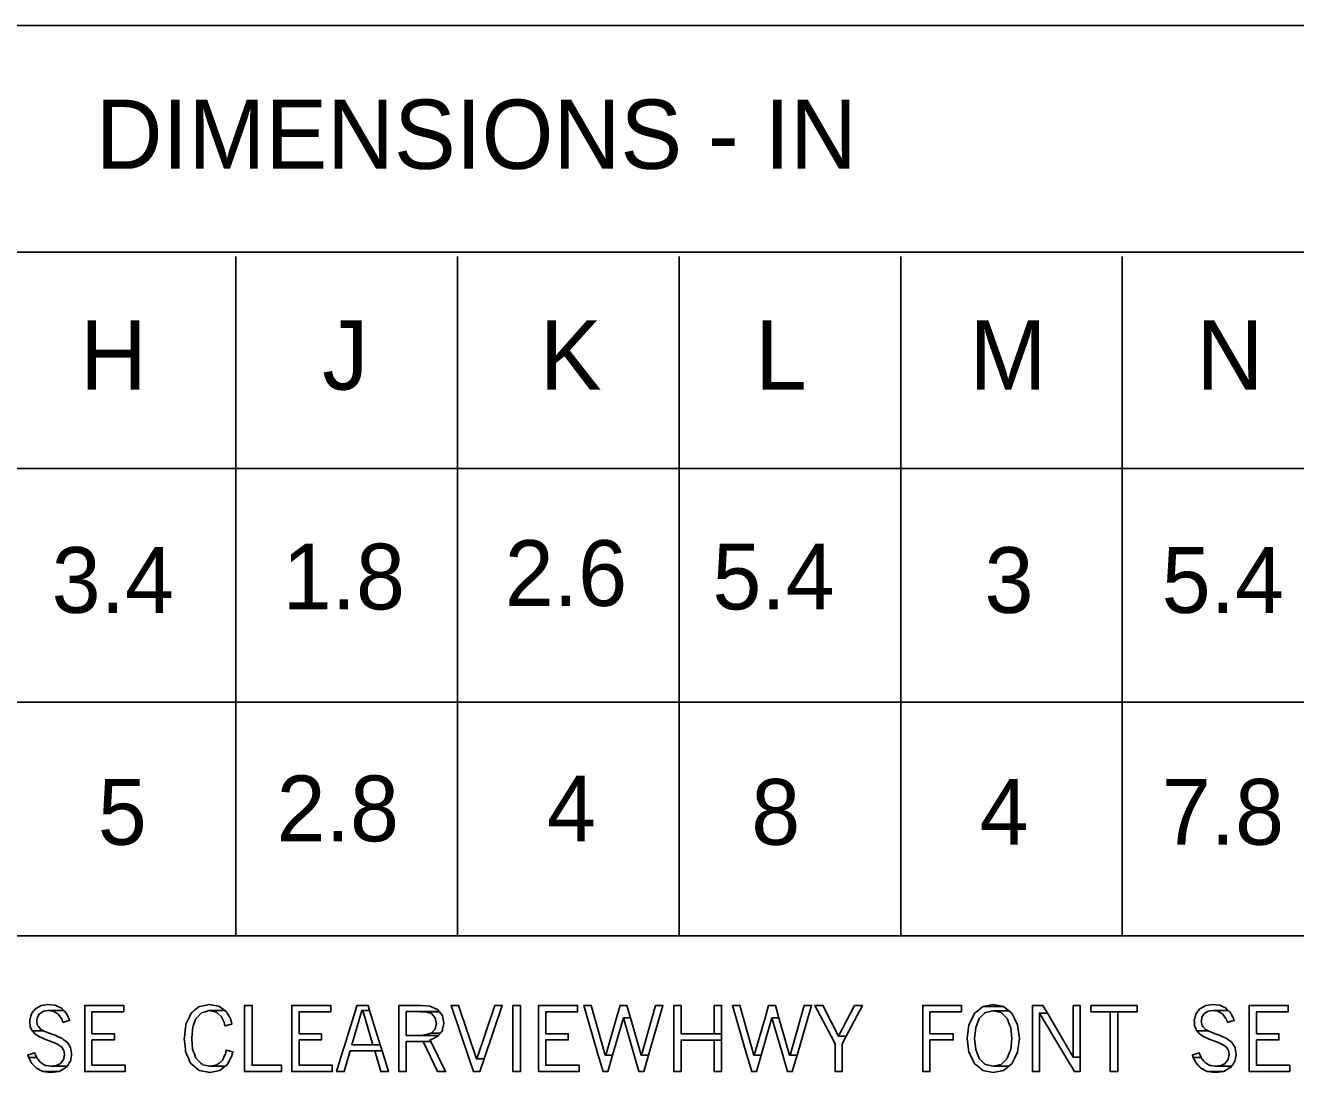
# Model space of a CAD drawing. Extents: x 0.013 to 0.187, y -0.092 to 0.261.
# Drawn here: x 0.09331 to 0.13917, y 0.0569 to 0.09473 of the extents above; entities that cross this region are included whole.
import ezdxf

# ---------------------------------------------------------------- set-up
doc = ezdxf.new("R2010")
doc.units = 0
doc.layers.add('3', color=7, linetype='Continuous')

msp = doc.modelspace()

# ---------------------------------------------------------------- linework, layer by layer
at = {"layer": '3'}
for p, q in [((0.032451, 0.094728), (0.186512, 0.094728)), ((0.186512, 0.086538), (0.032451, 0.086538)), ((0.100908, 0.086386), (0.100908, 0.061842)), ((0.108908, 0.086386), (0.108908, 0.061842)), ((0.116908, 0.086386), (0.116908, 0.061842)), ((0.124908, 0.086386), (0.124908, 0.061842)), ((0.132908, 0.086386), (0.132908, 0.061842)), ((0.032384, 0.078726), (0.186512, 0.078726)), ((0.032451, 0.070284), (0.186512, 0.070284)), ((0.032519, 0.061842), (0.186512, 0.061842))]:
    msp.add_line(p, q, dxfattribs=at)
for points in [[(0.093526, 0.058465), (0.093549, 0.058415), (0.093964, 0.058415), (0.093867, 0.058465), (0.093778, 0.05857), (0.093746, 0.058609), (0.093722, 0.058715), (0.093714, 0.058756), (0.093718, 0.058784), (0.093722, 0.058806), (0.09373, 0.058856), (0.093731, 0.058862), (0.093739, 0.05891), (0.093809, 0.059016), (0.093821, 0.059034), (0.093832, 0.059041), (0.093848, 0.059051), (0.093958, 0.059118), (0.093961, 0.059119), (0.094131, 0.059146), (0.09469, 0.059146), (0.094631, 0.059208), (0.094611, 0.059229), (0.094411, 0.059325), (0.094379, 0.05934), (0.094125, 0.059367), (0.094125, 0.059367), (0.093968, 0.05934), (0.093878, 0.059325), (0.093707, 0.059229), (0.093668, 0.059208), (0.093618, 0.059146), (0.093596, 0.059119), (0.093595, 0.059118), (0.09354, 0.059051), (0.093532, 0.059041), (0.093529, 0.059034), (0.093524, 0.059016), (0.093493, 0.05891), (0.093479, 0.058862), (0.093477, 0.058856), (0.093462, 0.058806), (0.093463, 0.058784), (0.093465, 0.058756), (0.093468, 0.058715), (0.093476, 0.058609), (0.093478, 0.05857)], [(0.095448, 0.057172), (0.095448, 0.056942), (0.096911, 0.056942), (0.096911, 0.057172), (0.09571, 0.057172), (0.09571, 0.058085), (0.096522, 0.058085), (0.096522, 0.058306), (0.09571, 0.058306), (0.09571, 0.059103), (0.096856, 0.059103), (0.096856, 0.059329), (0.095448, 0.059329), (0.095448, 0.059103), (0.095448, 0.058306), (0.095448, 0.058085)], [(0.099593, 0.056975), (0.099961, 0.056904), (0.100325, 0.056975), (0.100329, 0.056978), (0.10052, 0.057131), (0.099972, 0.057131), (0.099705, 0.05719), (0.099701, 0.057191), (0.0997, 0.057192), (0.099699, 0.057192), (0.099642, 0.057249), (0.099641, 0.057249), (0.099535, 0.057355), (0.099465, 0.057423), (0.099439, 0.057494), (0.099409, 0.057576), (0.099388, 0.057633), (0.099379, 0.057658), (0.099345, 0.057751), (0.099313, 0.058135), (0.099312, 0.058158), (0.099349, 0.058539), (0.099368, 0.058592), (0.099388, 0.058651), (0.09939, 0.058656), (0.099414, 0.058722), (0.099457, 0.058841), (0.099479, 0.058864), (0.099528, 0.058915), (0.099658, 0.059051), (0.099664, 0.059057), (0.099762, 0.059087), (0.099832, 0.059108), (0.099832, 0.059108), (0.09994, 0.059141), (0.100513, 0.059141), (0.100313, 0.059287), (0.100313, 0.059287), (0.100284, 0.059308), (0.099942, 0.059367), (0.099941, 0.059367), (0.099675, 0.059308), (0.099578, 0.059287), (0.099403, 0.059141), (0.099364, 0.059108), (0.099339, 0.059087), (0.099303, 0.059057), (0.099296, 0.059051), (0.09923, 0.058915), (0.099205, 0.058864), (0.099194, 0.058841), (0.099136, 0.058722), (0.099104, 0.058656), (0.099102, 0.058651), (0.099095, 0.058592), (0.099089, 0.058539), (0.099045, 0.058158), (0.099043, 0.058135), (0.099083, 0.057751), (0.099093, 0.057658), (0.099096, 0.057633), (0.099121, 0.057576), (0.099158, 0.057494), (0.09919, 0.057423), (0.09922, 0.057355), (0.099268, 0.057249), (0.099333, 0.057192), (0.099335, 0.057191), (0.099336, 0.05719), (0.099403, 0.057131), (0.099578, 0.056978)], [(0.101221, 0.057172), (0.101221, 0.056942), (0.102557, 0.056942), (0.102557, 0.057172), (0.10149, 0.057172), (0.10149, 0.059329), (0.101221, 0.059329)], [(0.102924, 0.057172), (0.102924, 0.056942), (0.104387, 0.056942), (0.104387, 0.057172), (0.103185, 0.057172), (0.103185, 0.058085), (0.103997, 0.058085), (0.103997, 0.058306), (0.103185, 0.058306), (0.103185, 0.059103), (0.104331, 0.059103), (0.104331, 0.059329), (0.102924, 0.059329), (0.102924, 0.059103), (0.102924, 0.058306), (0.102924, 0.058085)], [(0.104771, 0.057685), (0.104542, 0.056942), (0.10482, 0.056942), (0.105033, 0.057685), (0.106184, 0.057685), (0.106116, 0.057906), (0.105097, 0.057906), (0.105454, 0.059149), (0.105733, 0.059149), (0.105678, 0.059329), (0.105277, 0.059329), (0.105222, 0.059149), (0.104839, 0.057906)], [(0.106791, 0.058024), (0.106791, 0.056942), (0.107051, 0.056942), (0.107051, 0.058024), (0.107949, 0.058024), (0.107918, 0.058086), (0.10802, 0.058122), (0.108207, 0.058228), (0.108222, 0.058246), (0.107051, 0.058246), (0.107051, 0.058249), (0.107051, 0.058264), (0.107051, 0.058332), (0.107051, 0.058428), (0.107051, 0.058472), (0.107051, 0.058676), (0.107051, 0.058696), (0.107051, 0.058887), (0.107051, 0.058964), (0.107051, 0.059034), (0.107051, 0.059093), (0.107051, 0.059104), (0.107051, 0.059106), (0.108243, 0.059106), (0.108183, 0.059179), (0.107907, 0.059298), (0.10759, 0.059326), (0.107461, 0.059329), (0.106791, 0.059329), (0.106791, 0.059326), (0.106791, 0.059298), (0.106791, 0.059179), (0.106791, 0.059106), (0.106791, 0.059104), (0.106791, 0.059093), (0.106791, 0.059034), (0.106791, 0.058964), (0.106791, 0.058887), (0.106791, 0.058696), (0.106791, 0.058676), (0.106791, 0.058472), (0.106791, 0.058428), (0.106791, 0.058332), (0.106791, 0.058264), (0.106791, 0.058249), (0.106791, 0.058246), (0.106791, 0.058228), (0.106791, 0.058122), (0.106791, 0.058086)], [(0.109329, 0.057395), (0.109482, 0.056942), (0.109714, 0.056942), (0.109867, 0.057395), (0.109592, 0.057395), (0.108947, 0.059329), (0.108677, 0.059329)], [(0.110255, 0.059329), (0.109611, 0.057395), (0.109867, 0.057395), (0.110524, 0.059329)], [(0.11091, 0.059329), (0.11091, 0.056942), (0.111178, 0.056942), (0.111178, 0.059329)], [(0.111834, 0.057172), (0.111834, 0.056942), (0.113297, 0.056942), (0.113297, 0.057172), (0.112096, 0.057172), (0.112096, 0.058085), (0.112908, 0.058085), (0.112908, 0.058306), (0.112096, 0.058306), (0.112096, 0.059103), (0.113242, 0.059103), (0.113242, 0.059329), (0.111834, 0.059329), (0.111834, 0.059103), (0.111834, 0.058306), (0.111834, 0.058085)], [(0.113992, 0.057538), (0.114165, 0.056942), (0.114336, 0.056942), (0.114508, 0.057538), (0.114243, 0.057538), (0.113735, 0.059329), (0.11347, 0.059329)], [(0.114647, 0.058879), (0.11426, 0.057538), (0.114508, 0.057538), (0.114898, 0.058879), (0.115149, 0.058879), (0.115019, 0.059329), (0.114777, 0.059329)], [(0.116061, 0.059329), (0.115553, 0.057538), (0.115804, 0.057538), (0.116326, 0.059329)], [(0.116721, 0.058076), (0.116721, 0.056942), (0.116981, 0.056942), (0.116981, 0.058076), (0.118439, 0.058076), (0.118439, 0.058308), (0.116981, 0.058308), (0.116981, 0.059329), (0.116721, 0.059329), (0.116721, 0.058308)], [(0.11818, 0.059329), (0.11818, 0.058308), (0.118439, 0.058308), (0.118439, 0.059329)], [(0.119356, 0.057538), (0.119529, 0.056942), (0.1197, 0.056942), (0.119872, 0.057538), (0.119607, 0.057538), (0.119099, 0.059329), (0.118834, 0.059329)], [(0.120011, 0.058879), (0.119624, 0.057538), (0.119872, 0.057538), (0.120262, 0.058879), (0.120513, 0.058879), (0.120383, 0.059329), (0.120141, 0.059329)], [(0.121425, 0.059329), (0.120917, 0.057538), (0.121168, 0.057538), (0.12169, 0.059329)], [(0.122539, 0.057948), (0.122539, 0.056942), (0.1228, 0.056942), (0.1228, 0.057948), (0.122945, 0.058225), (0.122669, 0.058225), (0.1221, 0.059329), (0.121812, 0.059329), (0.122393, 0.058225)], [(0.123238, 0.059329), (0.122669, 0.058225), (0.122945, 0.058225), (0.123526, 0.059329)], [(0.125704, 0.058083), (0.125704, 0.056942), (0.125966, 0.056942), (0.125966, 0.058083), (0.126808, 0.058083), (0.126808, 0.058308), (0.125966, 0.058308), (0.125966, 0.059103), (0.127102, 0.059103), (0.127102, 0.059329), (0.125704, 0.059329), (0.125704, 0.059103), (0.125704, 0.058308)], [(0.12788, 0.05698), (0.128251, 0.056903), (0.128622, 0.05698), (0.128811, 0.057133), (0.12825, 0.057133), (0.127968, 0.057197), (0.127939, 0.057225), (0.127747, 0.057409), (0.127657, 0.057637), (0.127617, 0.057738), (0.127575, 0.058135), (0.127617, 0.058532), (0.127657, 0.058633), (0.127747, 0.058861), (0.127939, 0.059045), (0.127968, 0.059073), (0.12825, 0.059138), (0.128811, 0.059138), (0.128622, 0.05929), (0.127879, 0.05929), (0.127691, 0.059138), (0.127611, 0.059073), (0.127577, 0.059045), (0.127485, 0.058861), (0.127373, 0.058633), (0.127359, 0.058532), (0.127308, 0.058135), (0.127359, 0.057738), (0.127373, 0.057637), (0.127485, 0.057409), (0.127577, 0.057225), (0.127611, 0.057197), (0.127691, 0.057133)], [(0.128251, 0.059367), (0.12788, 0.05929), (0.128622, 0.05929)], [(0.129667, 0.057465), (0.129667, 0.056942), (0.129915, 0.056942), (0.129915, 0.057465), (0.129915, 0.059054), (0.130203, 0.059054), (0.130041, 0.059329), (0.129667, 0.059329), (0.129667, 0.059054)], [(0.131137, 0.059329), (0.131137, 0.057465), (0.131385, 0.057465), (0.131385, 0.059329)], [(0.131779, 0.059329), (0.131779, 0.059099), (0.133442, 0.059099), (0.133442, 0.059329)], [(0.135571, 0.058465), (0.135594, 0.058415), (0.136009, 0.058415), (0.135912, 0.058465), (0.135823, 0.05857), (0.135791, 0.058609), (0.135768, 0.058715), (0.135759, 0.058756), (0.135764, 0.058784), (0.135767, 0.058806), (0.135776, 0.058856), (0.135777, 0.058862), (0.135785, 0.05891), (0.135854, 0.059016), (0.135867, 0.059034), (0.135878, 0.059041), (0.135894, 0.059051), (0.136004, 0.059118), (0.136006, 0.059119), (0.136177, 0.059146), (0.136735, 0.059146), (0.136677, 0.059208), (0.136657, 0.059229), (0.136456, 0.059325), (0.136425, 0.05934), (0.136171, 0.059367), (0.13617, 0.059367), (0.136013, 0.05934), (0.135924, 0.059325), (0.135752, 0.059229), (0.135714, 0.059208), (0.135663, 0.059146), (0.135641, 0.059119), (0.13564, 0.059118), (0.135585, 0.059051), (0.135577, 0.059041), (0.135575, 0.059034), (0.13557, 0.059016), (0.135538, 0.05891), (0.135524, 0.058862), (0.135523, 0.058856), (0.135508, 0.058806), (0.135509, 0.058784), (0.135511, 0.058756), (0.135514, 0.058715), (0.135521, 0.058609), (0.135524, 0.05857)], [(0.137494, 0.057172), (0.137494, 0.056942), (0.138957, 0.056942), (0.138957, 0.057172), (0.137756, 0.057172), (0.137756, 0.058085), (0.138567, 0.058085), (0.138567, 0.058306), (0.137756, 0.058306), (0.137756, 0.059103), (0.138901, 0.059103), (0.138901, 0.059329), (0.137494, 0.059329), (0.137494, 0.059103), (0.137494, 0.058306), (0.137494, 0.058085)], [(0.09465, 0.058756), (0.094666, 0.058715), (0.094807, 0.058756), (0.094904, 0.058784), (0.094897, 0.058806), (0.094881, 0.058856), (0.094879, 0.058862), (0.094854, 0.05891), (0.094799, 0.059016), (0.094789, 0.059034), (0.094785, 0.059041), (0.09478, 0.059051), (0.094716, 0.059118), (0.094715, 0.059119), (0.09469, 0.059146), (0.094131, 0.059146), (0.094303, 0.059119), (0.094313, 0.059118), (0.094432, 0.059051), (0.094449, 0.059041), (0.094461, 0.059034), (0.094494, 0.059016), (0.094572, 0.05891), (0.094608, 0.058862), (0.094612, 0.058856), (0.094631, 0.058806), (0.09464, 0.058784)], [(0.1005, 0.058651), (0.100515, 0.058592), (0.100742, 0.058651), (0.100763, 0.058656), (0.100744, 0.058722), (0.100744, 0.058722), (0.100708, 0.058841), (0.100702, 0.058864), (0.100671, 0.058915), (0.100592, 0.059051), (0.100592, 0.059051), (0.100589, 0.059057), (0.100571, 0.059087), (0.100559, 0.059108), (0.100513, 0.059141), (0.09994, 0.059141), (0.100097, 0.059108), (0.1002, 0.059087), (0.100232, 0.059057), (0.100239, 0.059051), (0.100388, 0.058915), (0.100412, 0.058864), (0.100423, 0.058841), (0.100482, 0.058722), (0.100499, 0.058656)], [(0.10549, 0.059149), (0.105846, 0.057906), (0.106116, 0.057906), (0.105733, 0.059149)], [(0.107569, 0.059104), (0.107757, 0.059093), (0.108255, 0.059093), (0.108246, 0.059104), (0.108245, 0.059104), (0.108243, 0.059106), (0.107458, 0.059106)], [(0.108057, 0.058428), (0.107957, 0.058332), (0.108288, 0.058332), (0.108362, 0.058428), (0.108371, 0.058472), (0.10841, 0.058676), (0.108414, 0.058696), (0.108377, 0.058887), (0.108362, 0.058964), (0.108304, 0.059034), (0.108255, 0.059093), (0.107757, 0.059093), (0.107965, 0.059034), (0.108031, 0.058964), (0.108106, 0.058887), (0.108143, 0.058696), (0.108147, 0.058676), (0.108102, 0.058472)], [(0.115287, 0.057538), (0.11546, 0.056942), (0.115631, 0.056942), (0.115804, 0.057538), (0.115536, 0.057538), (0.115149, 0.058879), (0.114898, 0.058879)], [(0.120651, 0.057538), (0.120824, 0.056942), (0.120995, 0.056942), (0.121168, 0.057538), (0.1209, 0.057538), (0.120513, 0.058879), (0.120262, 0.058879)], [(0.128532, 0.057197), (0.12825, 0.057133), (0.128811, 0.057133), (0.128891, 0.057197), (0.128891, 0.057197), (0.128925, 0.057225), (0.129016, 0.057409), (0.129129, 0.057637), (0.129142, 0.057738), (0.129194, 0.058135), (0.129142, 0.058532), (0.129129, 0.058633), (0.129016, 0.058861), (0.128925, 0.059045), (0.128891, 0.059073), (0.128891, 0.059073), (0.128811, 0.059138), (0.12825, 0.059138), (0.128532, 0.059073), (0.12856, 0.059045), (0.128753, 0.058861), (0.128843, 0.058633), (0.128883, 0.058532), (0.128925, 0.058135), (0.128883, 0.057738), (0.128843, 0.057637), (0.128753, 0.057409), (0.12856, 0.057225)], [(0.130867, 0.057465), (0.131181, 0.056942), (0.131385, 0.056942), (0.131385, 0.057465), (0.131137, 0.057465), (0.130203, 0.059054), (0.129915, 0.059054)], [(0.132475, 0.059099), (0.132475, 0.056942), (0.132745, 0.056942), (0.132745, 0.059099)], [(0.136696, 0.058756), (0.136712, 0.058715), (0.136853, 0.058756), (0.136949, 0.058784), (0.136942, 0.058806), (0.136927, 0.058856), (0.136925, 0.058862), (0.136899, 0.05891), (0.136844, 0.059016), (0.136834, 0.059034), (0.136831, 0.059041), (0.136826, 0.059051), (0.136762, 0.059118), (0.136761, 0.059119), (0.136735, 0.059146), (0.136176, 0.059146), (0.136348, 0.059119), (0.136358, 0.059118), (0.136477, 0.059051), (0.136495, 0.059041), (0.136507, 0.059034), (0.136539, 0.059016), (0.136617, 0.05891), (0.136653, 0.058862), (0.136658, 0.058856), (0.136677, 0.058806), (0.136685, 0.058784)], [(0.094414, 0.057156), (0.094222, 0.057131), (0.094809, 0.057131), (0.094826, 0.057156), (0.094833, 0.057166), (0.094879, 0.057236), (0.094889, 0.057251), (0.094888, 0.057251), (0.0949, 0.057269), (0.094933, 0.057318), (0.094942, 0.057373), (0.094948, 0.057406), (0.094955, 0.057446), (0.09497, 0.057531), (0.094971, 0.057541), (0.094973, 0.057546), (0.094976, 0.057563), (0.094955, 0.057702), (0.094941, 0.057798), (0.094921, 0.05783), (0.094858, 0.057933), (0.094817, 0.058001), (0.094794, 0.058018), (0.094664, 0.058113), (0.09462, 0.058145), (0.094495, 0.058198), (0.094376, 0.05825), (0.094256, 0.058293), (0.094074, 0.058359), (0.093964, 0.058415), (0.093548, 0.058415), (0.093601, 0.058359), (0.093662, 0.058293), (0.09373, 0.05825), (0.09381, 0.058198), (0.093933, 0.058145), (0.094006, 0.058113), (0.094264, 0.058018), (0.094303, 0.058001), (0.094461, 0.057933), (0.094615, 0.05783), (0.094635, 0.057798), (0.094696, 0.057702), (0.094717, 0.057563), (0.09472, 0.057546), (0.094719, 0.057541), (0.094716, 0.057531), (0.094699, 0.057446), (0.09469, 0.057406), (0.094684, 0.057373), (0.094639, 0.057318), (0.094599, 0.057269), (0.094584, 0.057251), (0.094573, 0.057236), (0.094433, 0.057166)], [(0.107535, 0.058249), (0.107449, 0.058246), (0.108222, 0.058246), (0.108224, 0.058249), (0.108236, 0.058264), (0.108288, 0.058332), (0.107957, 0.058332), (0.107739, 0.058264)], [(0.136459, 0.057156), (0.136267, 0.057131), (0.136855, 0.057131), (0.136871, 0.057156), (0.136878, 0.057166), (0.136924, 0.057236), (0.136934, 0.057251), (0.136934, 0.057251), (0.136946, 0.057269), (0.136978, 0.057318), (0.136988, 0.057373), (0.136994, 0.057406), (0.137, 0.057446), (0.137015, 0.057531), (0.137017, 0.057541), (0.137018, 0.057546), (0.137021, 0.057563), (0.137, 0.057702), (0.136986, 0.057798), (0.136967, 0.05783), (0.136904, 0.057933), (0.136862, 0.058001), (0.136839, 0.058018), (0.136709, 0.058113), (0.136665, 0.058145), (0.136541, 0.058198), (0.136422, 0.05825), (0.136301, 0.058293), (0.136119, 0.058359), (0.136009, 0.058415), (0.135594, 0.058415), (0.135646, 0.058359), (0.135707, 0.058293), (0.135775, 0.05825), (0.135856, 0.058198), (0.135978, 0.058145), (0.136051, 0.058113), (0.136309, 0.058018), (0.136348, 0.058001), (0.136506, 0.057933), (0.13666, 0.05783), (0.13668, 0.057798), (0.136742, 0.057702), (0.136763, 0.057563), (0.136765, 0.057546), (0.136764, 0.057541), (0.136762, 0.057531), (0.136744, 0.057446), (0.136736, 0.057406), (0.136729, 0.057373), (0.136684, 0.057318), (0.136645, 0.057269), (0.136629, 0.057251), (0.136618, 0.057236), (0.136479, 0.057166)], [(0.107665, 0.058024), (0.108188, 0.056942), (0.108478, 0.056942), (0.107949, 0.058024)], [(0.11818, 0.058076), (0.11818, 0.056942), (0.118439, 0.056942), (0.118439, 0.058076)], [(0.093395, 0.057531), (0.093426, 0.057446), (0.093714, 0.057446), (0.093671, 0.057531), (0.093667, 0.057541), (0.093666, 0.057546), (0.09366, 0.057563), (0.09366, 0.057563), (0.093642, 0.057621), (0.093641, 0.057621), (0.093461, 0.057563), (0.093408, 0.057546), (0.093392, 0.057541)], [(0.093704, 0.057064), (0.093933, 0.056947), (0.094529, 0.056947), (0.094727, 0.057064), (0.094789, 0.0571), (0.094809, 0.057131), (0.094222, 0.057131), (0.09408, 0.057156), (0.094079, 0.057156), (0.094024, 0.057166), (0.093909, 0.057236), (0.093885, 0.057251), (0.093856, 0.057269), (0.093812, 0.057318), (0.093764, 0.057373), (0.093764, 0.057373), (0.093735, 0.057406), (0.093714, 0.057446), (0.093426, 0.057446), (0.093447, 0.057406), (0.093464, 0.057373), (0.093492, 0.057318), (0.093518, 0.057269), (0.093527, 0.057251), (0.093541, 0.057236), (0.093607, 0.057166), (0.093616, 0.057156), (0.09364, 0.057131), (0.093669, 0.0571)], [(0.10023, 0.05719), (0.099972, 0.057131), (0.10052, 0.057131), (0.100594, 0.05719), (0.100595, 0.057191), (0.100595, 0.057191), (0.100597, 0.057192), (0.100626, 0.057249), (0.100681, 0.057355), (0.100717, 0.057423), (0.100754, 0.057494), (0.100777, 0.057576), (0.100794, 0.057633), (0.100801, 0.057658), (0.100562, 0.057711), (0.100549, 0.057658), (0.100543, 0.057633), (0.10053, 0.057576), (0.100489, 0.057494), (0.100455, 0.057423), (0.100422, 0.057355), (0.100299, 0.057249), (0.100232, 0.057192), (0.10023, 0.057191)], [(0.105921, 0.057685), (0.106134, 0.056942), (0.106412, 0.056942), (0.106184, 0.057685)], [(0.135441, 0.057531), (0.135472, 0.057446), (0.13576, 0.057446), (0.135716, 0.057531), (0.135713, 0.057541), (0.135711, 0.057546), (0.135706, 0.057563), (0.135705, 0.057563), (0.135687, 0.057621), (0.135687, 0.057621), (0.135506, 0.057563), (0.135454, 0.057546), (0.135437, 0.057541)], [(0.135749, 0.057064), (0.135979, 0.056947), (0.136575, 0.056947), (0.136773, 0.057064), (0.136835, 0.0571), (0.136855, 0.057131), (0.136267, 0.057131), (0.136125, 0.057156), (0.136125, 0.057156), (0.136069, 0.057166), (0.135954, 0.057236), (0.135931, 0.057251), (0.135901, 0.057269), (0.135858, 0.057318), (0.135809, 0.057373), (0.135809, 0.057373), (0.13578, 0.057406), (0.13576, 0.057446), (0.135471, 0.057446), (0.135492, 0.057406), (0.135509, 0.057373), (0.135538, 0.057318), (0.135563, 0.057269), (0.135573, 0.057251), (0.135586, 0.057236), (0.135652, 0.057166), (0.135662, 0.057156), (0.135686, 0.057131), (0.135714, 0.0571)], [(0.093938, 0.056946), (0.094215, 0.056903), (0.094528, 0.056946), (0.094529, 0.056947), (0.093933, 0.056947)], [(0.135983, 0.056946), (0.136261, 0.056903), (0.136574, 0.056946), (0.136575, 0.056947), (0.135978, 0.056947)]]:
    msp.add_lwpolyline(points, close=True, dxfattribs=at)

# ---------------------------------------------------------------- texts
for s, height, p in [('DIMENSIONS - IN', 0.00249975, (0.095845, 0.089547)), ('H', 0.0025, (0.095275, 0.081571)), ('J', 0.0025, (0.104022, 0.081571)), ('K', 0.0025, (0.11188, 0.081571)), ('L', 0.0025, (0.119653, 0.081571)), ('M', 0.0025, (0.127392, 0.081571)), ('N', 0.0025, (0.13559, 0.081571)), ('2.6', 0.0023752, (0.110616, 0.073758)), ('3.4', 0.0023752, (0.094256, 0.073508)), ('1.8', 0.0023752, (0.102594, 0.073633)), ('5.4', 0.0023752, (0.118112, 0.073633)), ('3', 0.002375, (0.127936, 0.073508)), ('5.4', 0.0023752, (0.134334, 0.073508)), ('5', 0.002375, (0.095923, 0.065133)), ('2.8', 0.0023752, (0.102378, 0.065258)), ('4', 0.002375, (0.112133, 0.065258)), ('8', 0.002375, (0.119514, 0.065133)), ('4', 0.002375, (0.127765, 0.065133)), ('7.8', 0.0023752, (0.134332, 0.065133))]:
    msp.add_text(s, height=height, dxfattribs=at).set_placement(p)

doc.saveas('drawing.dxf')
